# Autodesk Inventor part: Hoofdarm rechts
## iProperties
Created: 2007-06
Part Number: Hoofdarm rechts
Material: Steel
Document SubType Name: Modeling
Designer: Phil Trethewie
Author: Phil Trethewie
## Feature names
1. Sweep1
2. Extrusion1
